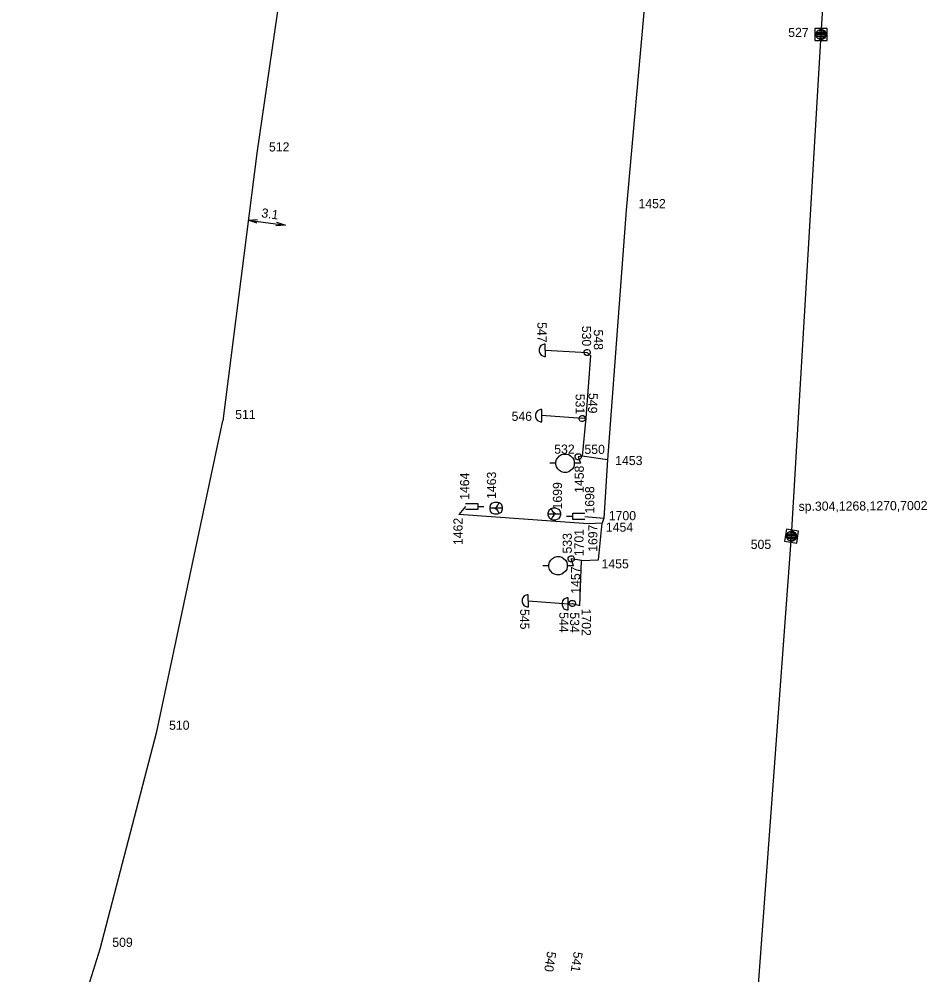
# Model space of a CAD drawing. Extents: x -535557 to -534097, y -1142175 to -1136716.
# Drawn here: x -534522.6 to -534448.4, y -1141339.2 to -1141261 of the extents above; entities that cross this region are included whole.
import ezdxf

# ---------------------------------------------------------------- set-up
doc = ezdxf.new("R2010")
doc.units = 0
doc.layers.add('Default', color=7, linetype='Continuous')
doc.layers.add('SS_SZDC', color=7, linetype='Continuous')

# ---------------------------------------------------------------- blocks, each defined once
blk = doc.blocks.new('POINT_DISPLAY')
at = {"layer": 'Default'}
blk.add_line((0, 0), (0, 0), dxfattribs=at)

msp = doc.modelspace()

# ---------------------------------------------------------------- linework, layer by layer
at = {"layer": 'SS_SZDC'}
for p, q in [((-534457.039, -1141262.299), (-534454.64, -1141223.729)), ((-534500.17, -1141251.42), (-534503.189, -1141272.02)), ((-534471, -1141254.649), (-534472.97, -1141276.659)), ((-534456.543, -1141261.796), (-534457.543, -1141261.803)), ((-534457.543, -1141261.803), (-534457.536, -1141262.803)), ((-534457.341, -1141262.001), (-534457.142, -1141261.9)), ((-534457.142, -1141261.9), (-534456.942, -1141261.899)), ((-534456.942, -1141261.899), (-534456.741, -1141261.998)), ((-534456.536, -1141262.796), (-534456.543, -1141261.796)), ((-534459.449, -1141303.34), (-534457.039, -1141262.299)), ((-534457.44, -1141262.202), (-534457.341, -1141262.001)), ((-534457.439, -1141262.402), (-534457.44, -1141262.202)), ((-534457.338, -1141262.601), (-534457.439, -1141262.402)), ((-534457.39, -1141262.202), (-534457.291, -1141262.101)), ((-534456.69, -1141262.197), (-534457.39, -1141262.202)), ((-534456.69, -1141262.297), (-534457.389, -1141262.302)), ((-534457.389, -1141262.402), (-534456.689, -1141262.397)), ((-534457.288, -1141262.501), (-534457.389, -1141262.402)), ((-534457.137, -1141262.7), (-534457.338, -1141262.601)), ((-534457.291, -1141262.101), (-534456.741, -1141262.098)), ((-534456.738, -1141262.498), (-534457.288, -1141262.501)), ((-534456.891, -1141261.999), (-534457.191, -1141262)), ((-534457.188, -1141262.6), (-534456.888, -1141262.599)), ((-534456.937, -1141262.699), (-534457.137, -1141262.7)), ((-534456.738, -1141262.598), (-534456.937, -1141262.699)), ((-534456.741, -1141262.098), (-534456.891, -1141261.999)), ((-534456.888, -1141262.599), (-534456.738, -1141262.498)), ((-534456.741, -1141261.998), (-534456.64, -1141262.197)), ((-534456.639, -1141262.397), (-534456.738, -1141262.598)), ((-534456.689, -1141262.397), (-534456.69, -1141262.197)), ((-534456.64, -1141262.197), (-534456.639, -1141262.397)), ((-534457.536, -1141262.803), (-534456.536, -1141262.796)), ((-534503.189, -1141272.02), (-534505.949, -1141293.909)), ((-534472.97, -1141276.659), (-534474.5, -1141297.09)), ((-534503.878, -1141277.48), (-534503.114, -1141277.436)), ((-534503.878, -1141277.48), (-534500.849, -1141277.906)), ((-534503.156, -1141277.733), (-534503.878, -1141277.48)), ((-534500.849, -1141277.906), (-534501.613, -1141277.95)), ((-534501.571, -1141277.653), (-534500.849, -1141277.906)), ((-534479.942, -1141287.732), (-534480.041, -1141287.882)), ((-534479.693, -1141287.63), (-534479.942, -1141287.732)), ((-534479.593, -1141287.63), (-534479.693, -1141287.63)), ((-534479.586, -1141288.629), (-534479.593, -1141287.63)), ((-534480.041, -1141287.882), (-534480.09, -1141288.033)), ((-534480.09, -1141288.033), (-534480.089, -1141288.233)), ((-534480.089, -1141288.233), (-534480.038, -1141288.382)), ((-534480.038, -1141288.382), (-534479.937, -1141288.532)), ((-534479.59, -1141288.129), (-534476.17, -1141288.309)), ((-534476.416, -1141288.354), (-534476.415, -1141288.242)), ((-534476.393, -1141288.421), (-534476.416, -1141288.354)), ((-534476.415, -1141288.242), (-534476.371, -1141288.153)), ((-534476.326, -1141288.511), (-534476.393, -1141288.421)), ((-534476.371, -1141288.153), (-534476.281, -1141288.086)), ((-534476.237, -1141288.555), (-534476.326, -1141288.511)), ((-534476.281, -1141288.086), (-534476.214, -1141288.063)), ((-534476.214, -1141288.063), (-534476.102, -1141288.064)), ((-534476.17, -1141288.309), (-534475.899, -1141288.559)), ((-534476.102, -1141288.064), (-534476.013, -1141288.108)), ((-534475.968, -1141288.466), (-534476.058, -1141288.533)), ((-534476.013, -1141288.108), (-534475.946, -1141288.198)), ((-534475.924, -1141288.377), (-534475.968, -1141288.466)), ((-534475.946, -1141288.198), (-534475.923, -1141288.265)), ((-534475.923, -1141288.265), (-534475.924, -1141288.377)), ((-534479.937, -1141288.532), (-534479.686, -1141288.63)), ((-534479.686, -1141288.63), (-534479.586, -1141288.629)), ((-534475.899, -1141288.559), (-534476.289, -1141293.7)), ((-534476.125, -1141288.556), (-534476.237, -1141288.555)), ((-534476.058, -1141288.533), (-534476.125, -1141288.556)), ((-534480.232, -1141293.082), (-534480.331, -1141293.232)), ((-534479.983, -1141292.98), (-534480.232, -1141293.082)), ((-534479.883, -1141292.98), (-534479.983, -1141292.98)), ((-534479.876, -1141293.979), (-534479.883, -1141292.98)), ((-534511.359, -1141319.329), (-534505.949, -1141293.909)), ((-534480.331, -1141293.232), (-534480.38, -1141293.383)), ((-534480.38, -1141293.383), (-534480.379, -1141293.583)), ((-534480.379, -1141293.583), (-534480.328, -1141293.732)), ((-534480.328, -1141293.732), (-534480.227, -1141293.882)), ((-534480.227, -1141293.882), (-534479.976, -1141293.98)), ((-534479.976, -1141293.98), (-534479.876, -1141293.979)), ((-534476.569, -1141293.719), (-534479.88, -1141293.479)), ((-534476.816, -1141293.764), (-534476.815, -1141293.652)), ((-534476.793, -1141293.831), (-534476.816, -1141293.764)), ((-534476.815, -1141293.652), (-534476.771, -1141293.563)), ((-534476.726, -1141293.921), (-534476.793, -1141293.831)), ((-534476.771, -1141293.563), (-534476.681, -1141293.496)), ((-534476.637, -1141293.965), (-534476.726, -1141293.921)), ((-534476.681, -1141293.496), (-534476.614, -1141293.473)), ((-534476.525, -1141293.966), (-534476.637, -1141293.965)), ((-534476.614, -1141293.473), (-534476.502, -1141293.474)), ((-534476.289, -1141293.7), (-534476.569, -1141293.719)), ((-534476.289, -1141293.7), (-534476.569, -1141296.799)), ((-534476.458, -1141293.943), (-534476.525, -1141293.966)), ((-534476.502, -1141293.474), (-534476.413, -1141293.518)), ((-534476.368, -1141293.876), (-534476.458, -1141293.943)), ((-534476.413, -1141293.518), (-534476.346, -1141293.608)), ((-534476.324, -1141293.787), (-534476.368, -1141293.876)), ((-534476.346, -1141293.608), (-534476.323, -1141293.675)), ((-534476.323, -1141293.675), (-534476.324, -1141293.787)), ((-534478.72, -1141297.27), (-534478.67, -1141297.07)), ((-534478.67, -1141297.07), (-534478.57, -1141296.92)), ((-534478.57, -1141296.92), (-534478.42, -1141296.77)), ((-534478.42, -1141296.77), (-534478.27, -1141296.67)), ((-534478.27, -1141296.67), (-534478.07, -1141296.62)), ((-534478.07, -1141296.62), (-534477.87, -1141296.62)), ((-534477.87, -1141296.62), (-534477.67, -1141296.67)), ((-534477.67, -1141296.67), (-534477.52, -1141296.77)), ((-534477.52, -1141296.77), (-534477.37, -1141296.92)), ((-534477.37, -1141296.92), (-534477.27, -1141297.07)), ((-534477.27, -1141297.07), (-534477.22, -1141297.27)), ((-534477.146, -1141296.884), (-534477.145, -1141296.772)), ((-534477.123, -1141296.951), (-534477.146, -1141296.884)), ((-534477.145, -1141296.772), (-534477.101, -1141296.683)), ((-534477.056, -1141297.041), (-534477.123, -1141296.951)), ((-534477.101, -1141296.683), (-534477.011, -1141296.616)), ((-534476.967, -1141297.085), (-534477.056, -1141297.041)), ((-534477.011, -1141296.616), (-534476.944, -1141296.593)), ((-534476.855, -1141297.086), (-534476.967, -1141297.085)), ((-534476.944, -1141296.593), (-534476.832, -1141296.594)), ((-534476.569, -1141296.799), (-534476.899, -1141296.84)), ((-534476.899, -1141296.84), (-534476.72, -1141297.37)), ((-534476.788, -1141297.063), (-534476.855, -1141297.086)), ((-534476.832, -1141296.594), (-534476.743, -1141296.638)), ((-534476.698, -1141296.996), (-534476.788, -1141297.063)), ((-534476.743, -1141296.638), (-534476.676, -1141296.728)), ((-534476.654, -1141296.907), (-534476.698, -1141296.996)), ((-534476.676, -1141296.728), (-534476.653, -1141296.795)), ((-534476.653, -1141296.795), (-534476.654, -1141296.907)), ((-534474.5, -1141297.09), (-534476.569, -1141296.799)), ((-534474.5, -1141297.09), (-534474.81, -1141301.86)), ((-534478.72, -1141297.37), (-534479.22, -1141297.37)), ((-534478.72, -1141297.47), (-534478.72, -1141297.27)), ((-534478.67, -1141297.67), (-534478.72, -1141297.47)), ((-534478.57, -1141297.82), (-534478.67, -1141297.67)), ((-534478.42, -1141297.97), (-534478.57, -1141297.82)), ((-534477.37, -1141297.82), (-534477.67, -1141298.07)), ((-534477.27, -1141297.67), (-534477.37, -1141297.82)), ((-534477.22, -1141297.47), (-534477.27, -1141297.67)), ((-534477.22, -1141297.27), (-534477.22, -1141297.37)), ((-534476.72, -1141297.37), (-534477.22, -1141297.37)), ((-534477.22, -1141297.37), (-534477.22, -1141297.47)), ((-534478.27, -1141298.07), (-534478.42, -1141297.97)), ((-534478.07, -1141298.12), (-534478.27, -1141298.07)), ((-534477.87, -1141298.12), (-534478.07, -1141298.12)), ((-534477.67, -1141298.07), (-534477.87, -1141298.12)), ((-534486.109, -1141300.909), (-534486.67, -1141301.569)), ((-534486.109, -1141300.659), (-534485.109, -1141300.659)), ((-534485.109, -1141300.659), (-534485.109, -1141301.159)), ((-534485.109, -1141300.909), (-534484.609, -1141300.909)), ((-534484.109, -1141300.949), (-534484.059, -1141300.799)), ((-534484.109, -1141301.149), (-534484.109, -1141300.949)), ((-534484.059, -1141300.799), (-534483.959, -1141300.649)), ((-534483.959, -1141300.649), (-534483.709, -1141300.549)), ((-534483.709, -1141300.549), (-534483.509, -1141300.549)), ((-534483.709, -1141301.049), (-534483.559, -1141300.949)), ((-534483.559, -1141300.949), (-534483.459, -1141300.799)), ((-534483.509, -1141300.549), (-534483.359, -1141300.599)), ((-534483.459, -1141300.799), (-534483.359, -1141300.599)), ((-534483.359, -1141300.599), (-534483.209, -1141300.699)), ((-534483.209, -1141300.699), (-534483.109, -1141300.949)), ((-534483.109, -1141300.949), (-534483.109, -1141301.149)), ((-534479.1, -1141301.07), (-534478.95, -1141301.02)), ((-534478.95, -1141301.02), (-534478.75, -1141301.02)), ((-534478.75, -1141301.02), (-534478.5, -1141301.12)), ((-534476.079, -1141302.329), (-534486.67, -1141301.569)), ((-534485.109, -1141301.159), (-534486.109, -1141301.159)), ((-534483.109, -1141301.049), (-534484.109, -1141301.049)), ((-534484.059, -1141301.299), (-534484.109, -1141301.149)), ((-534483.959, -1141301.449), (-534484.059, -1141301.299)), ((-534483.709, -1141301.549), (-534483.959, -1141301.449)), ((-534483.709, -1141301.049), (-534483.559, -1141301.149)), ((-534483.509, -1141301.549), (-534483.709, -1141301.549)), ((-534483.559, -1141301.149), (-534483.459, -1141301.299)), ((-534483.359, -1141301.499), (-534483.509, -1141301.549)), ((-534483.459, -1141301.299), (-534483.359, -1141301.499)), ((-534483.209, -1141301.399), (-534483.359, -1141301.499)), ((-534483.109, -1141301.149), (-534483.209, -1141301.399)), ((-534479.35, -1141301.42), (-534479.25, -1141301.17)), ((-534479.35, -1141301.62), (-534479.35, -1141301.42)), ((-534479.35, -1141301.52), (-534478.35, -1141301.52)), ((-534479.25, -1141301.87), (-534479.35, -1141301.62)), ((-534479.25, -1141301.17), (-534479.1, -1141301.07)), ((-534479, -1141301.27), (-534479.1, -1141301.07)), ((-534479, -1141301.77), (-534479.1, -1141301.97)), ((-534478.9, -1141301.42), (-534479, -1141301.27)), ((-534478.9, -1141301.62), (-534479, -1141301.77)), ((-534478.75, -1141301.52), (-534478.9, -1141301.42)), ((-534478.75, -1141301.52), (-534478.9, -1141301.62)), ((-534478.5, -1141301.12), (-534478.4, -1141301.27)), ((-534478.4, -1141301.77), (-534478.5, -1141301.92)), ((-534478.4, -1141301.27), (-534478.35, -1141301.42)), ((-534478.35, -1141301.62), (-534478.4, -1141301.77)), ((-534478.35, -1141301.42), (-534478.35, -1141301.62)), ((-534477.35, -1141301.719), (-534477.85, -1141301.719)), ((-534477.35, -1141301.969), (-534477.35, -1141301.469)), ((-534477.35, -1141301.469), (-534476.35, -1141301.469)), ((-534476.35, -1141301.719), (-534474.81, -1141301.86)), ((-534479.1, -1141301.97), (-534479.25, -1141301.87)), ((-534478.95, -1141302.02), (-534479.1, -1141301.97)), ((-534478.75, -1141302.02), (-534478.95, -1141302.02)), ((-534478.5, -1141301.92), (-534478.75, -1141302.02)), ((-534476.35, -1141301.969), (-534477.35, -1141301.969)), ((-534474.93, -1141302.29), (-534476.079, -1141302.329)), ((-534475.25, -1141305.29), (-534474.93, -1141302.29)), ((-534474.81, -1141301.86), (-534474.93, -1141302.29)), ((-534462.189, -1141340.389), (-534459.449, -1141303.34)), ((-534459.869, -1141302.77), (-534460.019, -1141303.759)), ((-534458.88, -1141302.92), (-534459.869, -1141302.77)), ((-534459.85, -1141303.242), (-534459.751, -1141303.041)), ((-534459.849, -1141303.442), (-534459.85, -1141303.242)), ((-534459.8, -1141303.242), (-534459.701, -1141303.141)), ((-534459.1, -1141303.237), (-534459.8, -1141303.242)), ((-534459.1, -1141303.337), (-534459.799, -1141303.342)), ((-534459.751, -1141303.041), (-534459.552, -1141302.94)), ((-534459.701, -1141303.141), (-534459.151, -1141303.138)), ((-534459.301, -1141303.039), (-534459.601, -1141303.04)), ((-534459.552, -1141302.94), (-534459.352, -1141302.939)), ((-534459.352, -1141302.939), (-534459.151, -1141303.038)), ((-534459.151, -1141303.138), (-534459.301, -1141303.039)), ((-534459.151, -1141303.038), (-534459.05, -1141303.237)), ((-534459.099, -1141303.437), (-534459.1, -1141303.237)), ((-534459.05, -1141303.237), (-534459.049, -1141303.437)), ((-534459.03, -1141303.909), (-534458.88, -1141302.92)), ((-534460.019, -1141303.759), (-534459.03, -1141303.909)), ((-534459.748, -1141303.641), (-534459.849, -1141303.442)), ((-534459.799, -1141303.442), (-534459.099, -1141303.437)), ((-534459.698, -1141303.541), (-534459.799, -1141303.442)), ((-534459.547, -1141303.74), (-534459.748, -1141303.641)), ((-534459.148, -1141303.538), (-534459.698, -1141303.541)), ((-534459.598, -1141303.64), (-534459.298, -1141303.639)), ((-534459.347, -1141303.739), (-534459.547, -1141303.74)), ((-534459.148, -1141303.638), (-534459.347, -1141303.739)), ((-534459.298, -1141303.639), (-534459.148, -1141303.538)), ((-534459.049, -1141303.437), (-534459.148, -1141303.638)), ((-534479.289, -1141305.66), (-534479.239, -1141305.46)), ((-534479.289, -1141305.86), (-534479.289, -1141305.66)), ((-534479.239, -1141305.46), (-534479.139, -1141305.31)), ((-534479.139, -1141305.31), (-534478.989, -1141305.16)), ((-534478.989, -1141305.16), (-534478.839, -1141305.06)), ((-534478.839, -1141305.06), (-534478.639, -1141305.01)), ((-534478.639, -1141305.01), (-534478.439, -1141305.01)), ((-534478.439, -1141305.01), (-534478.239, -1141305.06)), ((-534478.239, -1141305.06), (-534478.089, -1141305.16)), ((-534478.089, -1141305.16), (-534477.939, -1141305.31)), ((-534477.939, -1141305.31), (-534477.839, -1141305.46)), ((-534477.839, -1141305.46), (-534477.789, -1141305.66)), ((-534477.789, -1141305.66), (-534477.789, -1141305.76)), ((-534477.716, -1141305.234), (-534477.715, -1141305.122)), ((-534477.693, -1141305.301), (-534477.716, -1141305.234)), ((-534477.715, -1141305.122), (-534477.671, -1141305.033)), ((-534477.626, -1141305.391), (-534477.693, -1141305.301)), ((-534477.671, -1141305.033), (-534477.581, -1141304.966)), ((-534477.537, -1141305.435), (-534477.626, -1141305.391)), ((-534477.581, -1141304.966), (-534477.514, -1141304.943)), ((-534477.425, -1141305.436), (-534477.537, -1141305.435)), ((-534477.514, -1141304.943), (-534477.402, -1141304.944)), ((-534477.289, -1141305.76), (-534477.47, -1141305.19)), ((-534476.619, -1141305.329), (-534477.47, -1141305.19)), ((-534477.358, -1141305.413), (-534477.425, -1141305.436)), ((-534477.402, -1141304.944), (-534477.313, -1141304.988)), ((-534477.268, -1141305.346), (-534477.358, -1141305.413)), ((-534477.313, -1141304.988), (-534477.246, -1141305.078)), ((-534477.224, -1141305.257), (-534477.268, -1141305.346)), ((-534477.246, -1141305.078), (-534477.223, -1141305.145)), ((-534477.223, -1141305.145), (-534477.224, -1141305.257)), ((-534476.779, -1141309), (-534476.619, -1141305.329)), ((-534476.619, -1141305.329), (-534475.25, -1141305.29)), ((-534479.289, -1141305.76), (-534479.789, -1141305.76)), ((-534479.239, -1141306.06), (-534479.289, -1141305.86)), ((-534479.139, -1141306.21), (-534479.239, -1141306.06)), ((-534478.989, -1141306.36), (-534479.139, -1141306.21)), ((-534478.839, -1141306.46), (-534478.989, -1141306.36)), ((-534478.639, -1141306.51), (-534478.839, -1141306.46)), ((-534478.239, -1141306.46), (-534478.439, -1141306.51)), ((-534477.939, -1141306.21), (-534478.239, -1141306.46)), ((-534477.839, -1141306.06), (-534477.939, -1141306.21)), ((-534477.789, -1141305.86), (-534477.839, -1141306.06)), ((-534477.289, -1141305.76), (-534477.789, -1141305.76)), ((-534477.789, -1141305.76), (-534477.789, -1141305.86)), ((-534478.439, -1141306.51), (-534478.639, -1141306.51)), ((-534481.431, -1141308.382), (-534481.48, -1141308.533)), ((-534481.48, -1141308.533), (-534481.479, -1141308.733)), ((-534481.479, -1141308.733), (-534481.428, -1141308.882)), ((-534481.332, -1141308.232), (-534481.431, -1141308.382)), ((-534481.083, -1141308.13), (-534481.332, -1141308.232)), ((-534480.983, -1141308.13), (-534481.083, -1141308.13)), ((-534480.976, -1141309.129), (-534480.983, -1141308.13)), ((-534480.979, -1141308.629), (-534477.72, -1141308.879)), ((-534478.171, -1141308.632), (-534478.22, -1141308.783)), ((-534478.22, -1141308.783), (-534478.219, -1141308.983)), ((-534478.072, -1141308.482), (-534478.171, -1141308.632)), ((-534477.823, -1141308.38), (-534478.072, -1141308.482)), ((-534477.723, -1141308.38), (-534477.823, -1141308.38)), ((-534477.716, -1141309.379), (-534477.723, -1141308.38)), ((-534477.72, -1141308.879), (-534477.38, -1141308.84)), ((-534477.626, -1141308.884), (-534477.625, -1141308.772)), ((-534477.625, -1141308.772), (-534477.581, -1141308.683)), ((-534477.581, -1141308.683), (-534477.491, -1141308.616)), ((-534477.491, -1141308.616), (-534477.424, -1141308.593)), ((-534477.424, -1141308.593), (-534477.312, -1141308.594)), ((-534477.38, -1141308.84), (-534476.779, -1141309)), ((-534477.312, -1141308.594), (-534477.223, -1141308.638)), ((-534477.223, -1141308.638), (-534477.156, -1141308.728)), ((-534477.156, -1141308.728), (-534477.133, -1141308.795)), ((-534477.133, -1141308.795), (-534477.134, -1141308.907)), ((-534481.428, -1141308.882), (-534481.327, -1141309.032)), ((-534481.327, -1141309.032), (-534481.076, -1141309.13)), ((-534481.076, -1141309.13), (-534480.976, -1141309.129)), ((-534478.219, -1141308.983), (-534478.168, -1141309.132)), ((-534478.168, -1141309.132), (-534478.067, -1141309.282)), ((-534478.067, -1141309.282), (-534477.816, -1141309.38)), ((-534477.816, -1141309.38), (-534477.716, -1141309.379)), ((-534477.603, -1141308.951), (-534477.626, -1141308.884)), ((-534477.536, -1141309.041), (-534477.603, -1141308.951)), ((-534477.447, -1141309.085), (-534477.536, -1141309.041)), ((-534477.335, -1141309.086), (-534477.447, -1141309.085)), ((-534477.268, -1141309.063), (-534477.335, -1141309.086)), ((-534477.178, -1141308.996), (-534477.268, -1141309.063)), ((-534477.134, -1141308.907), (-534477.178, -1141308.996)), ((-534516, -1141337.09), (-534511.359, -1141319.329)), ((-534522.619, -1141358.309), (-534516, -1141337.09))]:
    msp.add_line(p, q, dxfattribs=at)

# ---------------------------------------------------------------- block references
for p in [(-534457.039, -1141262.299), (-534503.189, -1141272.02), (-534472.97, -1141276.659), (-534479.59, -1141288.129), (-534476.17, -1141288.309), (-534476.17, -1141288.309), (-534475.899, -1141288.559), (-534505.949, -1141293.909), (-534479.88, -1141293.479), (-534476.569, -1141293.719), (-534476.569, -1141293.719), (-534476.289, -1141293.7), (-534476.899, -1141296.84), (-534476.899, -1141296.84), (-534476.569, -1141296.799), (-534474.5, -1141297.09), (-534476.72, -1141297.37), (-534486.109, -1141300.909), (-534486.67, -1141301.569), (-534483.609, -1141301.049), (-534478.85, -1141301.52), (-534476.35, -1141301.719), (-534476.079, -1141302.329), (-534474.93, -1141302.29), (-534474.81, -1141301.86), (-534459.449, -1141303.34), (-534477.47, -1141305.19), (-534477.47, -1141305.19), (-534476.619, -1141305.329), (-534475.25, -1141305.29), (-534477.289, -1141305.76), (-534480.979, -1141308.629), (-534477.38, -1141308.84), (-534477.38, -1141308.84), (-534477.72, -1141308.879), (-534476.779, -1141309), (-534511.359, -1141319.329), (-534516, -1141337.09)]:
    msp.add_blockref('POINT_DISPLAY', p, dxfattribs=at)

# ---------------------------------------------------------------- texts
for s, p in [('527', (-534459.725, -1141262.507)), ('512', (-534502.189, -1141271.87)), ('1452', (-534471.97, -1141276.509)), ('511', (-534504.949, -1141293.759)), ('546', (-534482.347, -1141293.904)), ('532', (-534478.861, -1141296.597)), ('550', (-534476.392, -1141296.614)), ('1453', (-534473.874, -1141297.526)), ('1700', (-534474.401, -1141302.037)), ('1454', (-534474.635, -1141302.973)), ('505', (-534462.792, -1141304.387)), ('1455', (-534474.992, -1141305.974)), ('510', (-534510.359, -1141319.179)), ('509', (-534515, -1141336.94))]:
    msp.add_text(s, height=0.75, dxfattribs=at).set_placement(p)
for s, height, rotation, p in [('3.1', 0.75, 351.99946, (-534502.842, -1141277.247)), ('547', 0.75, 270, (-534480.237, -1141285.827)), ('530', 0.75, 270, (-534476.591, -1141286.129)), ('548', 0.75, 270, (-534475.62, -1141286.436)), ('531', 0.75, 270, (-534477.114, -1141291.692)), ('549', 0.75, 267.3, (-534476.035, -1141291.611)), ('1458', 0.75, 90, (-534476.441, -1141299.803)), ('1464', 0.75, 90, (-534485.812, -1141300.373)), ('1463', 0.75, 90, (-534483.615, -1141300.296)), ('1699', 0.75, 90, (-534478.221, -1141301.153)), ('1698', 0.75, 90, (-534475.586, -1141301.492)), ('sp.304,1268,1270,7002', 0.74999, 0.37563, (-534458.876, -1141301.273)), ('1462', 0.75, 90, (-534486.35, -1141304.071)), ('1697', 0.75, 90, (-534475.329, -1141304.622)), ('533', 0.75, 90, (-534477.422, -1141304.758)), ('1701', 0.75, 90, (-534476.466, -1141304.982)), ('1457', 0.75, 90, (-534476.738, -1141308.05)), ('545', 0.75, 270, (-534481.646, -1141309.301)), ('544', 0.75, 270, (-534478.445, -1141309.553)), ('534', 0.75, 270, (-534477.564, -1141309.571)), ('1702', 0.75, 270, (-534476.611, -1141309.265)), ('540', 0.75, 261, (-534479.428, -1141337.27)), ('541', 0.75, 261, (-534477.258, -1141337.29))]:
    msp.add_text(s, height=height, rotation=rotation, dxfattribs=at).set_placement(p)

doc.saveas('drawing.dxf')
